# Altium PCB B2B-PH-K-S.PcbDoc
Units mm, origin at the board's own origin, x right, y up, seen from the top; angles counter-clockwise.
Board outline 16.93 x 15.16 mm, 2 copper layers (Top Layer, Bottom Layer); 1 components, 0 nets, 2 pads, 0 vias.
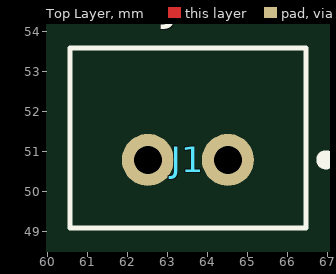
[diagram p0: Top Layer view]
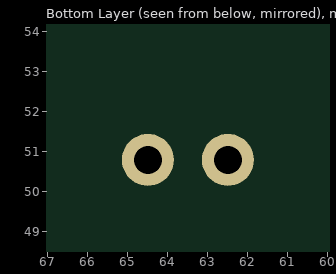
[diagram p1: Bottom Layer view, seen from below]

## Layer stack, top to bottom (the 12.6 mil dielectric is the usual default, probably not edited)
Top Layer: signal copper (thickness not stored)
Dielectric: dielectric 0.32, FR-4, Dk 4.8
Bottom Layer: signal copper (thickness not stored)

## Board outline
55.22,43.77 72.15,43.77 72.15,58.93 55.22,58.93

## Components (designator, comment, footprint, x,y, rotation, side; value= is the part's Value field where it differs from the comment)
J1 "B2B-PH-K-S" JST_B2B-PH-K-S_1x02_P2.00mm_Vertical 63.5,50.8 r0 top

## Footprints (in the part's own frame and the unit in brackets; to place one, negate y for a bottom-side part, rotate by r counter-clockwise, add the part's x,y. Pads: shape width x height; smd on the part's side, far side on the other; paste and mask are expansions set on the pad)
JST_B2B-PH-K-S_1x02_P2.00mm_Vertical [mm]
  round 1.3 hole 0.7: 1(1,0) 2(-1,0)
  silkscreen extent -2.95,-1.7 3.57,2.8

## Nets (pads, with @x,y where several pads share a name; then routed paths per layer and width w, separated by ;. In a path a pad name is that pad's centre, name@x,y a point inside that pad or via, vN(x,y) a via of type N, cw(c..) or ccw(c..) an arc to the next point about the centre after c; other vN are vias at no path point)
pads on no net: J1.1 J1.2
